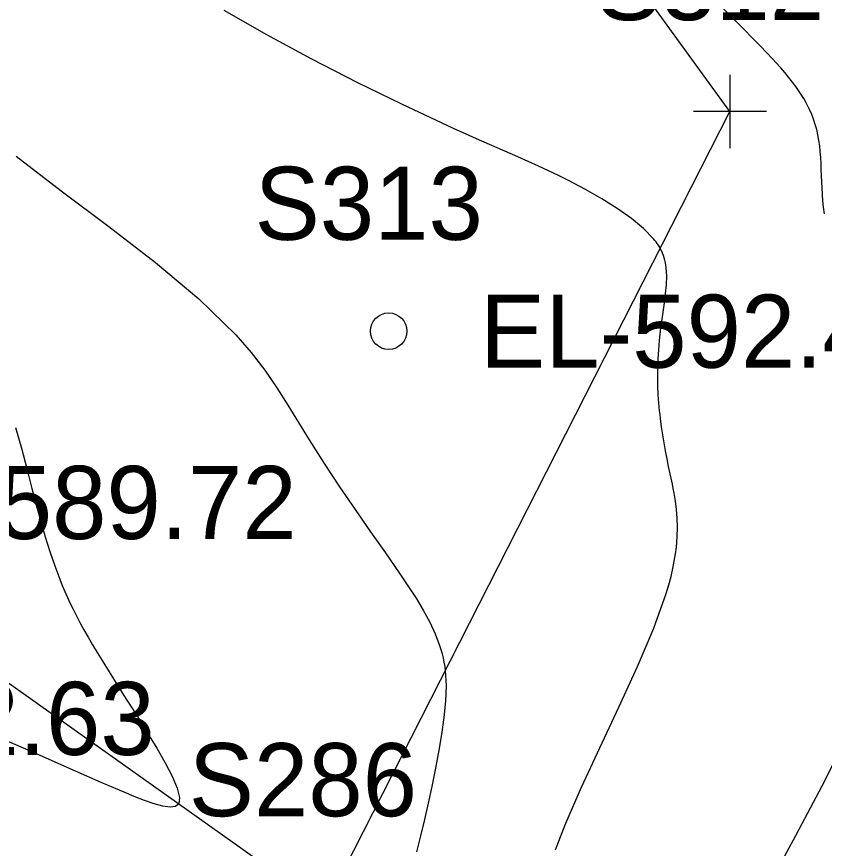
# Model space of a CAD drawing. Extents: x 1729869 to 1735532, y 648588 to 653771.
# Drawn here: x 1730520.14 to 1730564.33, y 652614.44 to 652659.96 of the extents above; entities that cross this region are included whole.
import ezdxf

# ---------------------------------------------------------------- set-up
doc = ezdxf.new("R2010")
doc.units = 0
for name, color, linetype in [('SURVEY - CENTERLINE - Preliminary', 7, 'Continuous'), ('SURVEY - CONTOURS - Intermediate with optional Text', 7, 'Continuous'), ('SURVEY - DTM - Breaklines', 7, 'Continuous'), ('SURVEY - DTM - Breaklines - Points - Elevations', 7, 'Continuous'), ('SURVEY - DTM - Breaklines - Points - Locators', 7, 'Continuous'), ('SURVEY - DTM - Breaklines - Points - Numbers', 7, 'Continuous'), ('SURVEY - DTM - Spot Points - Elevations', 7, 'Continuous'), ('SURVEY - DTM - Spot Points - Locators', 7, 'Continuous'), ('SURVEY - DTM - Spot Points - Point Numbers', 7, 'Continuous')]:
    doc.layers.add(name, color=color, linetype=linetype)

msp = doc.modelspace()

# ---------------------------------------------------------------- linework, layer by layer
at = {"layer": 'SURVEY - CENTERLINE - Preliminary'}
msp.add_arc((1731014.278, 652965.128), 500, 201.11545, 220.70969, dxfattribs=at)
at = {"layer": 'SURVEY - CONTOURS - Intermediate with optional Text'}
for points in [[(1730564.333, 652649.174), (1730564.287, 652649.54), (1730564.252, 652649.887), (1730564.226, 652650.233), (1730564.206, 652650.579), (1730564.19, 652650.923), (1730564.163, 652651.604), (1730564.149, 652651.93), (1730564.13, 652652.253), (1730564.107, 652652.571), (1730564.075, 652652.885), (1730564.033, 652653.193), (1730563.979, 652653.495), (1730563.913, 652653.784), (1730563.834, 652654.067), (1730563.741, 652654.345), (1730563.636, 652654.617), (1730563.518, 652654.884), (1730563.388, 652655.145), (1730563.297, 652655.314), (1730563.201, 652655.481), (1730563.099, 652655.647), (1730562.993, 652655.812), (1730562.881, 652655.976), (1730562.765, 652656.139), (1730562.575, 652656.392), (1730562.374, 652656.645), (1730562.163, 652656.9), (1730561.942, 652657.155), (1730561.712, 652657.412), (1730561.474, 652657.672), (1730561.162, 652658.005), (1730560.841, 652658.341), (1730560.511, 652658.681), (1730559.837, 652659.367), (1730558.287, 652660.936)], [(1730549.626, 652614.358), (1730549.891, 652615.068), (1730550.193, 652615.826), (1730551.049, 652617.794), (1730552.045, 652619.944), (1730553.093, 652622.177), (1730554.106, 652624.397), (1730554.998, 652626.504), (1730555.681, 652628.4), (1730555.821, 652628.873), (1730555.941, 652629.325), (1730556.04, 652629.755), (1730556.121, 652630.166), (1730556.184, 652630.559), (1730556.231, 652630.936), (1730556.276, 652631.497), (1730556.288, 652632.025), (1730556.273, 652632.525), (1730556.235, 652632.999), (1730556.178, 652633.453), (1730556.107, 652633.89), (1730556.061, 652634.136), (1730556.013, 652634.38), (1730555.862, 652635.099), (1730555.811, 652635.338), (1730555.724, 652635.769), (1730555.641, 652636.203), (1730555.563, 652636.64), (1730555.49, 652637.08), (1730555.424, 652637.522), (1730555.365, 652637.967), (1730555.339, 652638.182), (1730555.315, 652638.397), (1730555.294, 652638.614), (1730555.274, 652638.831), (1730555.258, 652639.051), (1730555.244, 652639.272), (1730555.223, 652639.754), (1730555.216, 652640.244), (1730555.221, 652640.739), (1730555.239, 652641.238), (1730555.27, 652641.737), (1730555.312, 652642.235), (1730555.349, 652642.585), (1730555.39, 652642.934), (1730555.437, 652643.282), (1730555.583, 652644.305), (1730555.645, 652644.805), (1730555.688, 652645.292), (1730555.702, 652645.763), (1730555.678, 652646.213), (1730555.66, 652646.354), (1730555.637, 652646.494), (1730555.608, 652646.628), (1730555.573, 652646.761), (1730555.531, 652646.893), (1730555.481, 652647.023), (1730555.422, 652647.152), (1730555.354, 652647.281), (1730555.303, 652647.369), (1730555.247, 652647.457), (1730555.187, 652647.544), (1730555.122, 652647.632), (1730555.053, 652647.72), (1730554.98, 652647.809), (1730554.439, 652648.362), (1730553.769, 652648.916), (1730552.996, 652649.463), (1730552.148, 652649.997), (1730551.252, 652650.509), (1730550.335, 652650.992), (1730549.789, 652651.263), (1730549.242, 652651.525), (1730548.69, 652651.781), (1730548.131, 652652.034), (1730547.56, 652652.287), (1730545.305, 652653.278), (1730544.703, 652653.545), (1730544.073, 652653.829), (1730543.41, 652654.131), (1730541.21, 652655.166), (1730538.799, 652656.347), (1730536.296, 652657.629), (1730533.818, 652658.964), (1730531.483, 652660.306)], [(1730520.103, 652652.328), (1730522.576, 652650.426), (1730525.173, 652648.477), (1730527.734, 652646.501), (1730530.104, 652644.521), (1730532.123, 652642.558), (1730532.968, 652641.58), (1730533.708, 652640.61), (1730534.369, 652639.648), (1730534.977, 652638.693), (1730536.135, 652636.799), (1730536.959, 652635.505), (1730537.808, 652634.23), (1730538.662, 652632.983), (1730539.503, 652631.777), (1730540.311, 652630.622), (1730541.067, 652629.529), (1730541.546, 652628.819), (1730541.988, 652628.136), (1730542.387, 652627.475), (1730542.738, 652626.828), (1730543.038, 652626.189), (1730543.281, 652625.55), (1730543.352, 652625.326), (1730543.415, 652625.099), (1730543.47, 652624.87), (1730543.518, 652624.636), (1730543.557, 652624.399), (1730543.588, 652624.155), (1730543.631, 652623.356), (1730543.604, 652622.501), (1730543.519, 652621.603), (1730543.388, 652620.671), (1730543.224, 652619.716), (1730543.039, 652618.75), (1730542.853, 652617.835), (1730542.659, 652616.923), (1730542.455, 652616.019), (1730542.24, 652615.127), (1730542.014, 652614.252)], [(1730520.078, 652637.474), (1730520.406, 652636.348), (1730520.697, 652635.233), (1730520.972, 652634.143), (1730521.21, 652633.231), (1730521.453, 652632.35), (1730521.703, 652631.502), (1730521.959, 652630.689), (1730522.224, 652629.915), (1730522.498, 652629.18), (1730522.636, 652628.836), (1730522.777, 652628.5), (1730522.922, 652628.171), (1730523.071, 652627.847), (1730523.225, 652627.527), (1730523.385, 652627.209), (1730523.594, 652626.808), (1730523.814, 652626.406), (1730524.044, 652625.998), (1730524.286, 652625.584), (1730524.54, 652625.159), (1730524.807, 652624.723), (1730525.19, 652624.108), (1730526.009, 652622.813), (1730526.436, 652622.139), (1730526.868, 652621.452), (1730527.3, 652620.757), (1730527.801, 652619.929), (1730528.26, 652619.129), (1730528.645, 652618.389), (1730528.92, 652617.745), (1730529.052, 652617.23), (1730529.007, 652616.879), (1730528.826, 652616.733), (1730528.53, 652616.695), (1730528.138, 652616.749), (1730527.668, 652616.877), (1730527.14, 652617.061), (1730526.574, 652617.283), (1730526.022, 652617.513), (1730525.459, 652617.754), (1730524.761, 652618.056), (1730523.356, 652618.672), (1730520.762, 652619.815), (1730519.713, 652620.271)], [(1730561.292, 652612.408), (1730562.763, 652615.146), (1730564.201, 652617.875), (1730565.683, 652620.811)]]:
    msp.add_lwpolyline(points, dxfattribs=at)
at = {"layer": 'SURVEY - DTM - Breaklines'}
msp.add_lwpolyline([(1730488.683, 652751.18), (1730492.115, 652738.294), (1730482.6, 652711.757), (1730471.692, 652681.616), (1730472.615, 652659.855), (1730505.777, 652633.375), (1730536.998, 652611.204), (1730559.167, 652654.774), (1730537.649, 652684.424), (1730515.497, 652721.048), (1730496.309, 652730.082), (1730490.18, 652752.403)], dxfattribs=at)
at = {"layer": 'SURVEY - DTM - Breaklines - Points - Locators'}
for p, q in [((1730559.167, 652656.774), (1730559.167, 652652.774)), ((1730561.167, 652654.774), (1730557.167, 652654.774))]:
    msp.add_line(p, q, dxfattribs=at)
at = {"layer": 'SURVEY - DTM - Spot Points - Locators'}
msp.add_circle((1730540.492, 652642.75), 1, dxfattribs=at)

# ---------------------------------------------------------------- texts
at = {"layer": 'SURVEY - DTM - Breaklines - Points - Elevations'}
for s, p in [('EL-589.72', (1730510.777, 652631.375)), ('EL-592.63', (1730503.011, 652619.557))]:
    msp.add_text(s, height=4, dxfattribs=at).set_placement(p)
at = {"layer": 'SURVEY - DTM - Breaklines - Points - Numbers'}
for s, p in [('S312', (1730551.831, 652659.774)), ('S286', (1730529.552, 652616.204))]:
    msp.add_text(s, height=4, dxfattribs=at).set_placement(p)
at = {"layer": 'SURVEY - DTM - Spot Points - Elevations'}
msp.add_text('EL-592.44', height=4, dxfattribs=at).set_placement((1730545.492, 652640.75))
at = {"layer": 'SURVEY - DTM - Spot Points - Point Numbers'}
msp.add_text('S313', height=4, dxfattribs=at).set_placement((1730533.156, 652647.75))

doc.saveas('drawing.dxf')
